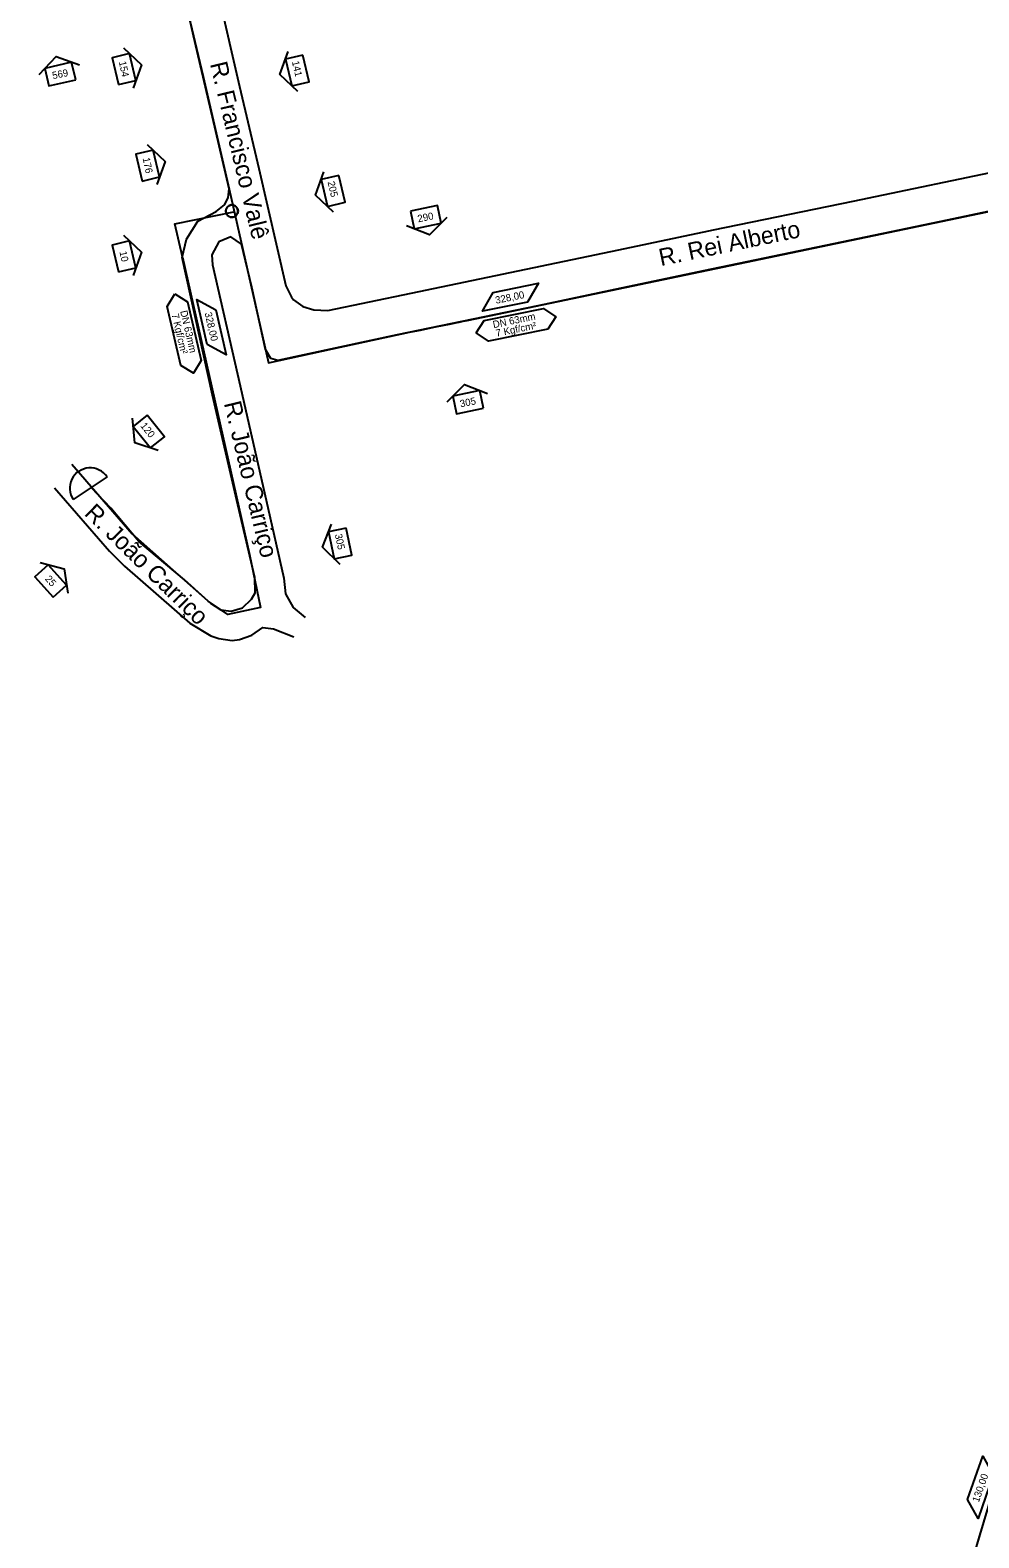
# Model space of a CAD drawing. Extents: x 656692 to 673945, y 7585994 to 7599066.
# Drawn here: x 669634 to 670030, y 7592467 to 7593096 of the extents above; entities that cross this region are included whole.
import ezdxf

# ---------------------------------------------------------------- set-up
doc = ezdxf.new("R2010")
doc.units = 0
for name, color, linetype in [('FORMATO', 7, 'Continuous'), ('LOGRADOURO', 7, 'Continuous'), ('LOGRADOURO_TEXTO', 7, 'Continuous'), ('NUM_REF', 7, 'Continuous'), ('SIMBOLO', 7, 'Continuous'), ('TEXTO', 7, 'Continuous'), ('TUBO_PEAD_GN_63', 7, 'Continuous')]:
    doc.layers.add(name, color=color, linetype=linetype)

# ---------------------------------------------------------------- blocks, each defined once
blk = doc.blocks.new('INTERLIGACAO_5')
at = {"layer": 'SIMBOLO'}
blk.add_circle((0, 0), 1.28, dxfattribs=at)
for start, end in [(0, 180), (180, 0)]:
    blk.add_arc((0, 0), 1.28, start, end, dxfattribs=at)
blk = doc.blocks.new('NUM_REF_1')
at = {"layer": 'NUM_REF'}
blk.add_lwpolyline([(-4.3125, 0.9375), (0, 3.75), (4.3125, 0.9375)], dxfattribs=at)
blk.add_lwpolyline([(2.875, -1.875), (2.875, 1.875), (-2.875, 1.875), (-2.875, -1.875)], close=True, dxfattribs=at)

msp = doc.modelspace()

# ---------------------------------------------------------------- linework, layer by layer
at = {"layer": 'LOGRADOURO'}
for points in [[(669651.58, 7592915.12), (669676.83, 7592886.04), (669709.49, 7592857.19), (669713.79, 7592854.38), (669718.11, 7592853.76), (669722.89, 7592855.21), (669726.63, 7592858.83), (669728.11, 7592861.39), (669727.95, 7592867.77), (669720.94, 7592898.23), (669710.33, 7592943.91), (669697.68, 7593001.32), (669699.48, 7593008.99), (669704.25, 7593016.47), (669711.85, 7593020.53), (669715.37, 7593023.38), (669716.86, 7593026.22), (669717.22, 7593030.04), (669710.35, 7593060), (669702.46, 7593093.9), (669698.65, 7593110.55)], [(669712.92, 7593110.27), (669721.63, 7593072.67), (669729.58, 7593038.58), (669740.91, 7592989.61), (669743.21, 7592984.83), (669744.08, 7592983.73), (669748.07, 7592980.91), (669752.54, 7592979.54), (669758.37, 7592979.32), (669793.14, 7592986.52), (669837.87, 7592995.77), (669879.82, 7593004.54), (669917.42, 7593012.48), (669919.36, 7593012.9), (669977.55, 7593024.93), (670044.25, 7593038.8)], [(670049.13, 7593023.72), (670016.81, 7593016.94), (669966.13, 7593006.45), (669918.53, 7592996.47), (669880.77, 7592988.6), (669845.99, 7592981.2), (669787.33, 7592969.09), (669737.51, 7592958.36), (669734.6, 7592959.19), (669732.48, 7592962.96), (669726.79, 7592988.99), (669722.47, 7593006.95), (669718, 7593010.05), (669712.99, 7593007.86), (669709.99, 7593002.44), (669710.27, 7592998.29), (669720.71, 7592952.63), (669732.72, 7592900.12), (669740.14, 7592867.63), (669740.74, 7592861.05), (669743.97, 7592855.29), (669749.03, 7592851.2)], [(669644.39, 7592905.24), (669667.3, 7592878.86), (669673.61, 7592872.63), (669700.9, 7592848.8), (669709.59, 7592843.44), (669712.95, 7592842.34), (669718.55, 7592841.56), (669721.65, 7592841.96), (669726.79, 7592843.82), (669731.26, 7592846.94), (669735.73, 7592846.46), (669744.29, 7592843.12)], [(670140.67, 7592814.77), (670143.3, 7592813.13), (670147.59, 7592806.78), (670149.37, 7592800.72), (670148, 7592794.55), (670142.54, 7592783.47), (670126.74, 7592751.73), (670115.57, 7592726.99), (670105.38, 7592702.43), (670092.03, 7592667.42), (670081.67, 7592638.9), (670075.01, 7592618.77), (670070.43, 7592603.29), (670069.38, 7592599.53), (670054.1, 7592547.86), (670045.88, 7592520.43), (670039.4, 7592498.41), (670028.44, 7592462)]]:
    msp.add_lwpolyline(points, dxfattribs=at)
at = {"layer": 'SIMBOLO'}
for points in [[(669694.61, 7592986.19), (669699.86, 7592982.92), (669705.6, 7592958.33), (669702.34, 7592953.08), (669697.08, 7592956.34), (669691.34, 7592980.93), (669694.61, 7592986.19)], [(669820.27, 7592969.88), (669823.69, 7592975.04), (669848.43, 7592980.08), (669853.59, 7592976.67), (669850.18, 7592971.51), (669825.43, 7592966.47), (669820.27, 7592969.88)]]:
    msp.add_lwpolyline(points, dxfattribs=at)
for points in [[(669841.74, 7592982.8), (669822.9, 7592978.96), (669827.44, 7592986.77), (669846.27, 7592990.61)], [(669708.13, 7592965.1), (669703.76, 7592983.82), (669711.7, 7592979.51), (669716.07, 7592960.79)], [(670036.06, 7592493.33), (670029.74, 7592475.18), (670025.34, 7592483.07), (670031.67, 7592501.22)]]:
    msp.add_lwpolyline(points, close=True, dxfattribs=at)
at = {"layer": 'TUBO_PEAD_GN_63'}
msp.add_line((669666.31, 7592909.79), (669652.17, 7592900.33), dxfattribs=at)
for points in [[(669691.34, 7593140.14), (669706.41, 7593076.97), (669717.25, 7593029.9), (669733.74, 7592957.42), (669760.34, 7592963.31), (669792.45, 7592970.16), (669797.09, 7592971.1), (669803.41, 7592972.41), (669809.96, 7592973.76), (669811.63, 7592974.11), (669813.25, 7592974.44), (669814.86, 7592974.78), (669816.63, 7592975.14), (670108.84, 7593036.1)], [(669697.83, 7593001.61), (669694.61, 7593015.39), (669719.28, 7593020.49)], [(669697.78, 7593001.54), (669725.7, 7592877.44), (669730.3, 7592855.31), (669716.7, 7592852.44), (669708.58, 7592857.98), (669698.58, 7592866.83), (669679.65, 7592882.92), (669667.84, 7592896.83), (669659.82, 7592905.26)], [(670030.53, 7592468.97), (670028.44, 7592461.89)]]:
    msp.add_lwpolyline(points, dxfattribs=at)
msp.add_arc((669659.24, 7592905.06), 8.51, 33.80135, 213.80135, dxfattribs=at)

# ---------------------------------------------------------------- block references
at = {"layer": 'FORMATO'}
for p, xscale, yscale, rotation in [((669646.82, 7593077.91), 2.0000000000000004, 1.9999999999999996, 13.244366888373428), ((669673.38, 7593079.98), 2, 2, -76.67539240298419), ((669745.74, 7593079.42), 2, 2, 103.25233689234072), ((669683.29, 7593039.75), 2, 2, -76.67539240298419), ((669760.63, 7593029.16), 2, 2, 103.25233689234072), ((669799.32, 7593018.21), 2, 2, -168.497058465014), ((669673.38, 7593001.84), 2, 2, -76.67539240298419), ((669817, 7592940.99), 1.9999999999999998, 2.0000000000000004, 11.642526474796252), ((669683.75, 7592928.75), 2, 2, 128.60782862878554), ((669763.59, 7592882.03), 1.9999999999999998, 2.0000000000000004, 102.1520438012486), ((669642.81, 7592866.39), 2, 2, -47.91357892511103)]:
    msp.add_blockref('NUM_REF_1', p, dxfattribs=dict(at, xscale=xscale, yscale=yscale, rotation=rotation))
at = {"layer": 'SIMBOLO', "xscale": 2, "yscale": 2, "rotation": -14.764722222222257}
msp.add_blockref('INTERLIGACAO_5', (669718.4, 7593020.75), dxfattribs=at)

# ---------------------------------------------------------------- texts
for s, rotation, p in [('154', 281.82028, (669671.25, 7593083.02)), ('141', 283.25234, (669743.41, 7593083.1)), ('569', 11.74004, (669643.78, 7593075.78)), ('176', 281.82028, (669681.16, 7593042.79)), ('205', 283.25234, (669758.3, 7593032.84)), ('290', 11.50294, (669796.19, 7593016.04)), ('10', 281.82028, (669671.49, 7593003.74)), ('305', 11.64253, (669813.88, 7592938.82)), ('120', 308.60783, (669680.07, 7592931.08)), ('305', 282.15204, (669761.33, 7592885.76)), ('25', 310.5821, (669640.24, 7592867.15))]:
    msp.add_text(s, height=3, rotation=rotation).set_placement(p)
at = {"layer": 'LOGRADOURO_TEXTO'}
for s, rotation, p in [('R. Francisco Valê', 283.53624, (669709.24, 7593082.21)), ('R. Rei Alberto', 11.74598, (669897.35, 7592997.75)), ('R. João Carriço', 283.53624, (669715.02, 7592940.55)), ('R. João Carriço', 315.68228, (669656.46, 7592894.15))]:
    msp.add_text(s, height=7.2, rotation=rotation, dxfattribs=at).set_placement(p)
at = {"layer": 'TEXTO'}
for s, rotation, p in [('328,00', 11.51235, (669828.61, 7592982.04)), ('7 Kgf/cm²', 283.14313, (669693.22, 7592977.61)), ('DN 63mm', 283.14313, (669696.82, 7592978.93)), ('328,00', 283.14313, (669707, 7592978.2)), ('DN 63mm', 11.51235, (669827.59, 7592971.88)), ('7 Kgf/cm²', 11.51235, (669828.8, 7592968.25)), ('130,00', 70.78543, (670030.01, 7592481.66))]:
    msp.add_text(s, height=3, rotation=rotation, dxfattribs=at).set_placement(p)

doc.saveas('drawing.dxf')
